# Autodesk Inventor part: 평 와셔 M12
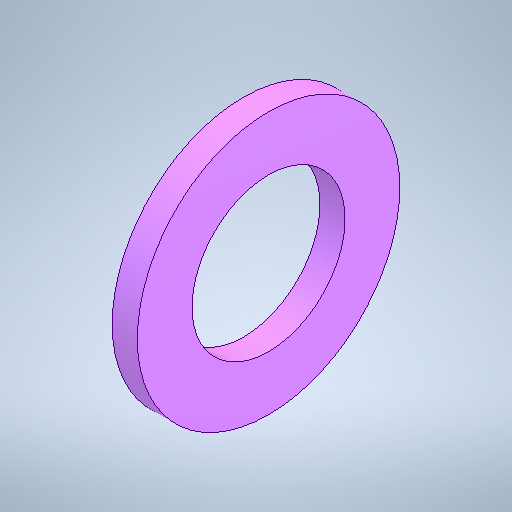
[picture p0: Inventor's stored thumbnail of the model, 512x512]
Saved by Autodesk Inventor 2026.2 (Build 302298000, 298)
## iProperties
Created: 2026-06
Part Number: 평 와셔 M12
Material: 강철, 연강
Description: 평면 와셔
Document SubType Name: Modeling
Designer: sec7
Density: 7.85 g/cm^3
Appearance: 기본값
Author: jhkim
Sending System: Autodesk Inventor 2027
Preprocessor: ST-DEVELOPER v20.1
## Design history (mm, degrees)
feature "Solid1"
node "솔리드1"
